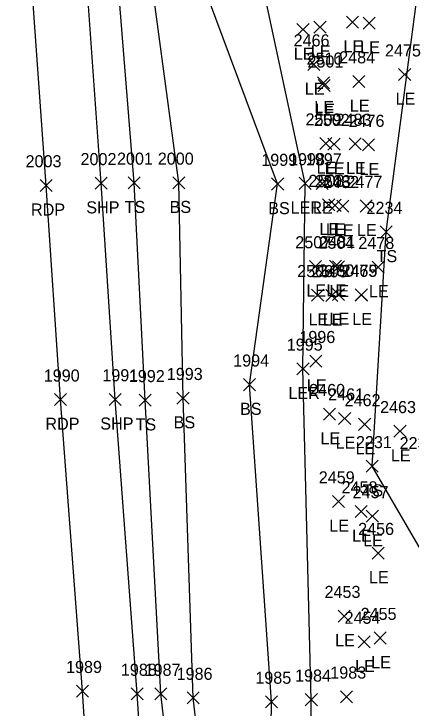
# Model space of a CAD drawing. Extents: x 1650221 to 1650634, y 244606 to 249996.
# Drawn here: x 1650421.8 to 1650487.6, y 245461.1 to 245576.1 of the extents above; entities that cross this region are included whole.
import ezdxf

# ---------------------------------------------------------------- set-up
doc = ezdxf.new("R2010")
doc.units = 0
for name, color, linetype in [('L_A', 7, 'Continuous'), ('L_I', 7, 'Continuous'), ('L_TIC', 7, 'Continuous'), ('LARO', 7, 'Continuous'), ('LELB', 7, 'Continuous'), ('P_A', 7, 'Continuous'), ('P_I', 7, 'Continuous'), ('P_TIC', 7, 'Continuous'), ('PET', 7, 'Continuous'), ('PSP', 7, 'Continuous')]:
    doc.layers.add(name, color=color, linetype=linetype)

msp = doc.modelspace()

# ---------------------------------------------------------------- linework, layer by layer
at = {"layer": 'L_TIC'}
for points in [[(1650471.47, 245572.91), (1650473.47, 245574.91)], [(1650473.47, 245572.91), (1650471.47, 245574.91)], [(1650476.86, 245573.75), (1650478.86, 245575.75)], [(1650478.86, 245573.75), (1650476.86, 245575.75)], [(1650479.63, 245573.58), (1650481.63, 245575.58)], [(1650481.63, 245573.58), (1650479.63, 245575.58)], [(1650468.65, 245572.5), (1650470.65, 245574.5)], [(1650470.65, 245572.5), (1650468.65, 245574.5)], [(1650470.46, 245566.72), (1650472.46, 245568.72)], [(1650472.46, 245566.72), (1650470.46, 245568.72)], [(1650485.49, 245565.05), (1650487.49, 245567.05)], [(1650487.49, 245565.05), (1650485.49, 245567.05)], [(1650477.91, 245563.91), (1650479.91, 245565.91)], [(1650479.91, 245563.91), (1650477.91, 245565.91)], [(1650472.03, 245563.7), (1650474.03, 245565.7)], [(1650474.03, 245563.7), (1650472.03, 245565.7)], [(1650472.17, 245563.22), (1650474.17, 245565.22)], [(1650474.17, 245563.22), (1650472.17, 245565.22)], [(1650472.43, 245553.62), (1650474.43, 245555.62)], [(1650474.43, 245553.62), (1650472.43, 245555.62)], [(1650473.79, 245553.53), (1650475.79, 245555.53)], [(1650475.79, 245553.53), (1650473.79, 245555.53)], [(1650477.31, 245553.57), (1650479.31, 245555.57)], [(1650479.31, 245553.57), (1650477.31, 245555.57)], [(1650479.51, 245553.39), (1650481.51, 245555.39)], [(1650481.51, 245553.39), (1650479.51, 245555.39)], [(1650440.71, 245547.12), (1650442.71, 245549.12)], [(1650442.71, 245547.12), (1650440.71, 245549.12)], [(1650448.11, 245547.12), (1650450.11, 245549.12)], [(1650450.11, 245547.12), (1650448.11, 245549.12)], [(1650464.46, 245546.92), (1650466.46, 245548.92)], [(1650466.46, 245546.92), (1650464.46, 245548.92)], [(1650469.03, 245547.03), (1650471.03, 245549.03)], [(1650471.03, 245547.03), (1650469.03, 245549.03)], [(1650471.81, 245547.01), (1650473.81, 245549.01)], [(1650473.81, 245547.01), (1650471.81, 245549.01)], [(1650472.9, 245543.45), (1650474.9, 245545.45)], [(1650474.9, 245543.45), (1650472.9, 245545.45)], [(1650473.96, 245543.39), (1650475.96, 245545.39)], [(1650475.96, 245543.39), (1650473.96, 245545.39)], [(1650475.26, 245543.25), (1650477.26, 245545.25)], [(1650477.26, 245543.25), (1650475.26, 245545.25)], [(1650479.1, 245543.28), (1650481.1, 245545.28)], [(1650481.1, 245543.28), (1650479.1, 245545.28)], [(1650482.43, 245538.97), (1650484.43, 245540.97)], [(1650484.43, 245538.97), (1650482.43, 245540.97)], [(1650470.72, 245533.27), (1650472.72, 245535.27)], [(1650472.72, 245533.27), (1650470.72, 245535.27)], [(1650474.05, 245533.3), (1650476.05, 245535.3)], [(1650476.05, 245533.3), (1650474.05, 245535.3)], [(1650474.54, 245533.19), (1650476.54, 245535.19)], [(1650476.54, 245533.19), (1650474.54, 245535.19)], [(1650481.08, 245533.16), (1650483.08, 245535.16)], [(1650483.08, 245533.16), (1650481.08, 245535.16)], [(1650471.09, 245528.5), (1650473.09, 245530.5)], [(1650473.09, 245528.5), (1650471.09, 245530.5)], [(1650473.43, 245528.45), (1650475.43, 245530.45)], [(1650475.43, 245528.45), (1650473.43, 245530.45)], [(1650474.55, 245528.6), (1650476.55, 245530.6)], [(1650476.55, 245528.6), (1650474.55, 245530.6)], [(1650478.31, 245528.54), (1650480.31, 245530.54)], [(1650480.31, 245528.54), (1650478.31, 245530.54)], [(1650478.32, 245528.53), (1650480.32, 245530.53)], [(1650480.32, 245528.53), (1650478.32, 245530.53)], [(1650470.8, 245517.57), (1650472.8, 245519.57)], [(1650472.8, 245517.57), (1650470.8, 245519.57)], [(1650468.65, 245516.3), (1650470.65, 245518.3)], [(1650470.65, 245516.3), (1650468.65, 245518.3)], [(1650459.79, 245513.67), (1650461.79, 245515.67)], [(1650461.79, 245513.67), (1650459.79, 245515.67)], [(1650442.52, 245511.09), (1650444.52, 245513.09)], [(1650444.52, 245511.09), (1650442.52, 245513.09)], [(1650448.79, 245511.44), (1650450.79, 245513.44)], [(1650450.79, 245511.44), (1650448.79, 245513.44)], [(1650473.06, 245508.79), (1650475.06, 245510.79)], [(1650475.06, 245508.79), (1650473.06, 245510.79)], [(1650475.56, 245508.06), (1650477.56, 245510.06)], [(1650477.56, 245508.06), (1650475.56, 245510.06)], [(1650478.86, 245507.1), (1650480.86, 245509.1)], [(1650480.86, 245507.1), (1650478.86, 245509.1)], [(1650484.71, 245505.96), (1650486.71, 245507.96)], [(1650486.71, 245505.96), (1650484.71, 245507.96)], [(1650480.11, 245500.15), (1650482.11, 245502.15)], [(1650482.11, 245500.15), (1650480.11, 245502.15)], [(1650474.53, 245494.31), (1650476.53, 245496.31)], [(1650476.53, 245494.31), (1650474.53, 245496.31)], [(1650478.3, 245492.66), (1650480.3, 245494.66)], [(1650480.3, 245492.66), (1650478.3, 245494.66)], [(1650480.13, 245491.86), (1650482.13, 245493.86)], [(1650482.13, 245491.86), (1650480.13, 245493.86)], [(1650481.09, 245485.77), (1650483.09, 245487.77)], [(1650483.09, 245485.77), (1650481.09, 245487.77)], [(1650475.48, 245475.33), (1650477.48, 245477.33)], [(1650477.48, 245475.33), (1650475.48, 245477.33)], [(1650481.45, 245471.69), (1650483.45, 245473.69)], [(1650483.45, 245471.69), (1650481.45, 245473.69)], [(1650478.8, 245471.04), (1650480.8, 245473.04)], [(1650480.8, 245471.04), (1650478.8, 245473.04)], [(1650445.12, 245462.42), (1650447.12, 245464.42)], [(1650447.12, 245462.42), (1650445.12, 245464.42)], [(1650450.48, 245461.76), (1650452.48, 245463.76)], [(1650452.48, 245461.76), (1650450.48, 245463.76)], [(1650470.03, 245461.47), (1650472.03, 245463.47)], [(1650472.03, 245461.47), (1650470.03, 245463.47)], [(1650475.86, 245461.96), (1650477.86, 245463.96)], [(1650477.86, 245461.96), (1650475.86, 245463.96)], [(1650463.45, 245461.11), (1650465.45, 245463.11)], [(1650465.45, 245461.11), (1650463.45, 245463.11)]]:
    msp.add_lwpolyline(points, dxfattribs=at)
at = {"layer": 'LARO'}
msp.add_lwpolyline([(1650491, 245121.86), (1650493.61, 245139.73), (1650488.81, 245187.64), (1650492.44, 245198.75), (1650485.3, 245221.37), (1650479.96, 245259.68), (1650476.93, 245285.6), (1650472.44, 245315.86), (1650475.26, 245352.64), (1650477.44, 245377.75), (1650471.06, 245430.31), (1650471.03, 245462.47), (1650469.65, 245517.3), (1650470.03, 245548.03), (1650459.64, 245596.52), (1650458.35, 245631.93), (1650449.5, 245684.33)], dxfattribs=at)
at = {"layer": 'LELB'}
for points in [[(1650489.71, 244991.22), (1650489.69, 245009.71), (1650486.09, 245047.64), (1650483.87, 245079.25), (1650480.92, 245116.18), (1650479.42, 245140.42), (1650476.29, 245187.3), (1650474, 245221.05), (1650469.02, 245258.31), (1650465.71, 245285.05), (1650462.26, 245315.54), (1650460.48, 245356.55), (1650462.16, 245378.82), (1650455.67, 245427.55), (1650451.48, 245462.76), (1650449.79, 245512.44), (1650449.11, 245548.12), (1650443.42, 245590.47), (1650442.32, 245632.05), (1650435.43, 245684.43)], [(1650471.05, 245115.28), (1650468.74, 245140.33), (1650464.89, 245185.98), (1650463.25, 245221.34), (1650461.37, 245257.85), (1650459.32, 245284.8), (1650456.97, 245315.55), (1650454.6, 245356.59), (1650452.98, 245378.54), (1650450.43, 245426.58), (1650446.12, 245463.42), (1650443.52, 245512.09), (1650441.71, 245548.12), (1650438.37, 245589.38), (1650434.29, 245631.65), (1650429.68, 245683.37)], [(1650504.95, 245130.46), (1650502.44, 245141.72), (1650499.16, 245156.24), (1650498.93, 245181.82), (1650503.83, 245194.54), (1650500.59, 245204.36), (1650497.12, 245222.6), (1650494.12, 245240.25), (1650494.91, 245258.03), (1650492.2, 245286.73), (1650496.63, 245312.12), (1650498.98, 245327.58), (1650495.95, 245351.61), (1650501.94, 245378.34), (1650498.52, 245407), (1650497.68, 245445.99), (1650496.14, 245475.39), (1650481.11, 245501.15), (1650483.43, 245539.97), (1650491.3, 245600.05), (1650490.9, 245637.99), (1650484.15, 245671.67)], [(1650493.15, 245007.74), (1650488.13, 245047.67), (1650486.59, 245079.09), (1650485.35, 245117.44), (1650483.97, 245140), (1650485.34, 245188.31), (1650482.43, 245221.37), (1650477.25, 245258), (1650473.1, 245285.62), (1650468.47, 245315.46), (1650468.65, 245355.64), (1650472.97, 245377.88), (1650463.98, 245429.04), (1650464.45, 245462.11), (1650460.79, 245514.67), (1650465.46, 245547.92), (1650447.43, 245596.3), (1650450.46, 245632.25)]]:
    msp.add_lwpolyline(points, dxfattribs=at)
at = {"layer": 'P_TIC'}
for points in [[(1650426.14, 245546.69), (1650428.14, 245548.69)], [(1650428.14, 245546.69), (1650426.14, 245548.69)], [(1650435.23, 245547.05), (1650437.23, 245549.05)], [(1650437.23, 245547.05), (1650435.23, 245549.05)], [(1650428.51, 245511.19), (1650430.51, 245513.19)], [(1650430.51, 245511.19), (1650428.51, 245513.19)], [(1650437.55, 245511.23), (1650439.55, 245513.23)], [(1650439.55, 245511.23), (1650437.55, 245513.23)], [(1650432.13, 245462.89), (1650434.13, 245464.89)], [(1650434.13, 245462.89), (1650432.13, 245464.89)], [(1650441.19, 245462.43), (1650443.19, 245464.43)], [(1650443.19, 245462.43), (1650441.19, 245464.43)]]:
    msp.add_lwpolyline(points, dxfattribs=at)
at = {"layer": 'PET'}
msp.add_lwpolyline([(1650458.15, 245114.32), (1650456.62, 245139.84), (1650453.42, 245185.54), (1650451.1, 245220.97), (1650448.32, 245256.66), (1650446.89, 245283.96), (1650444.13, 245314.19), (1650440.98, 245355.92), (1650439.55, 245378.58), (1650435.64, 245425.9), (1650433.13, 245463.89), (1650429.51, 245512.19), (1650427.14, 245547.69), (1650424.3, 245587.11), (1650421.18, 245630.65), (1650417.91, 245681.78)], dxfattribs=at)
at = {"layer": 'PSP'}
msp.add_lwpolyline([(1650467.35, 245115.19), (1650465.66, 245140.38), (1650462.4, 245185.76), (1650459.93, 245221.23), (1650457.1, 245257.2), (1650455.22, 245284.62), (1650453.41, 245314.94), (1650449.96, 245356.27), (1650448.46, 245377.97), (1650444.62, 245426.85), (1650442.19, 245463.43), (1650438.55, 245512.23), (1650436.23, 245548.05), (1650433.37, 245588.35), (1650430.25, 245631.19), (1650426.21, 245683.01)], dxfattribs=at)

# ---------------------------------------------------------------- texts
at = {"layer": 'L_A'}
for s, p in [('LE', (1650476.35, 245569.75)), ('LE', (1650479.12, 245569.58)), ('LE', (1650468.13, 245568.5)), ('LE', (1650470.95, 245568.91)), ('LE', (1650469.95, 245562.72)), ('LE', (1650484.98, 245561.05)), ('LE', (1650471.52, 245559.7)), ('LE', (1650471.66, 245559.22)), ('LE', (1650477.4, 245559.91)), ('LE', (1650471.91, 245549.62)), ('LE', (1650473.27, 245549.53)), ('LE', (1650476.79, 245549.57)), ('LE', (1650479, 245549.39)), ('TS', (1650440.12, 245543.12)), ('BS', (1650447.56, 245543.12)), ('LER', (1650467.61, 245543.03)), ('LE', (1650471.3, 245543.01)), ('BS', (1650463.9, 245542.92)), ('LE', (1650472.38, 245539.45)), ('LE', (1650473.45, 245539.39)), ('LE', (1650474.75, 245539.25)), ('LE', (1650478.58, 245539.28)), ('TS', (1650481.84, 245534.97)), ('LE', (1650470.21, 245529.27)), ('LE', (1650473.54, 245529.3)), ('LE', (1650474.03, 245529.19)), ('LE', (1650480.56, 245529.16)), ('LE', (1650474.04, 245524.6)), ('LE', (1650470.57, 245524.5)), ('LE', (1650472.92, 245524.45)), ('LE', (1650477.8, 245524.54)), ('LE', (1650477.81, 245524.53)), ('LE', (1650470.29, 245513.57)), ('LER', (1650467.24, 245512.3)), ('BS', (1650459.23, 245509.67)), ('BS', (1650448.23, 245507.44)), ('TS', (1650441.93, 245507.09)), ('LE', (1650472.55, 245504.79)), ('LE', (1650475.05, 245504.06)), ('LE', (1650478.35, 245503.1)), ('LE', (1650484.2, 245501.96)), ('TS', (1650479.52, 245496.15)), ('LE', (1650474.01, 245490.31)), ('LE', (1650477.78, 245488.66)), ('LE', (1650479.62, 245487.86)), ('LE', (1650480.58, 245481.77)), ('LE', (1650474.97, 245471.33)), ('LE', (1650480.94, 245467.69)), ('LE', (1650478.28, 245467.04))]:
    msp.add_text(s, height=2, dxfattribs=at).set_placement(p)
at = {"layer": 'L_I'}
for s, p in [('2466', (1650468.1, 245570.72)), ('2475', (1650483.23, 245569.05)), ('2510', (1650470.25, 245567.7)), ('2501', (1650470.4, 245567.22)), ('2484', (1650475.65, 245567.91)), ('2509', (1650470.08, 245557.62)), ('2502', (1650471.45, 245557.53)), ('2483', (1650475.05, 245557.57)), ('2476', (1650477.19, 245557.39)), ('2001', (1650438.86, 245551.12)), ('2000', (1650445.61, 245551.12)), ('1998', (1650467.34, 245551.03)), ('1999', (1650462.75, 245550.92)), ('1997', (1650470.12, 245551.01)), ('2508', (1650470.56, 245547.45)), ('2503', (1650471.62, 245547.39)), ('2482', (1650473, 245547.25)), ('2477', (1650476.84, 245547.28)), ('2234', (1650480.17, 245542.97)), ('2507', (1650468.38, 245537.27)), ('2481', (1650472.35, 245537.3)), ('2504', (1650472.2, 245537.19)), ('2478', (1650478.82, 245537.16)), ('2506', (1650468.69, 245532.5)), ('2505', (1650471.09, 245532.45)), ('2480', (1650472.21, 245532.6)), ('2465', (1650476.01, 245532.53)), ('2479', (1650476.05, 245532.54)), ('1996', (1650469.05, 245521.57)), ('1995', (1650466.96, 245520.3)), ('1994', (1650458.1, 245517.67)), ('1993', (1650447.1, 245515.44)), ('1992', (1650440.82, 245515.09)), ('2460', (1650470.67, 245512.79)), ('2461', (1650473.82, 245512.06)), ('2462', (1650476.55, 245511.1)), ('2463', (1650482.41, 245509.96)), ('2231', (1650478.42, 245504.15)), ('2232', (1650485.65, 245503.99)), ('2459', (1650472.26, 245498.31)), ('2458', (1650476.04, 245496.66)), ('2457', (1650477.87, 245495.86)), ('2456', (1650478.78, 245489.77)), ('2453', (1650473.22, 245479.33)), ('2455', (1650479.19, 245475.69)), ('2454', (1650476.54, 245475.04)), ('1987', (1650443.43, 245466.42)), ('1983', (1650474.17, 245465.96)), ('1986', (1650448.73, 245465.76)), ('1985', (1650461.76, 245465.11)), ('1984', (1650468.34, 245465.47))]:
    msp.add_text(s, height=2, dxfattribs=at).set_placement(p)
at = {"layer": 'P_A'}
for s, p in [('SHP', (1650433.77, 245543.05)), ('RDP', (1650424.62, 245542.69)), ('RDP', (1650427, 245507.19)), ('SHP', (1650436.09, 245507.23))]:
    msp.add_text(s, height=2, dxfattribs=at).set_placement(p)
at = {"layer": 'P_I'}
for s, p in [('2002', (1650432.82, 245551.05)), ('2003', (1650423.72, 245550.69)), ('1990', (1650426.73, 245515.19)), ('1991', (1650436.43, 245515.23)), ('1989', (1650430.42, 245466.89)), ('1988', (1650439.5, 245466.43))]:
    msp.add_text(s, height=2, dxfattribs=at).set_placement(p)

doc.saveas('drawing.dxf')
